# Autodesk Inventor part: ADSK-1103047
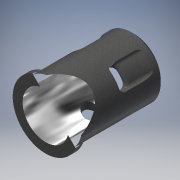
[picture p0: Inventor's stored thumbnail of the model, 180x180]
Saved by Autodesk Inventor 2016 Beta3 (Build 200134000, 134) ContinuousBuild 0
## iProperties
Shininess: 54.0
Length Units: 11269
Angle Units: 11279
Time Units: 11290
Mass Units: 11286
Length Display Precision: 2
Angle Display Precision: 2
Compacted: True
Created: 2000-07
Part Number: ADSK-1103047
Document SubType Name: Modeling
Description: ENGINE SLEEVE - REAR
Mass: 20.4003 g
Surface Area: 29.807 cm^2
Volume: 2.59876 cm^3
Density: 7.85 g/cm^3
Material: Cast Steel
Appearance: Brass
Density: 0.0
Volumn: 0.0
Area: 0.0
PropertySet Name: Model Information
Control State: 0
Master: False
Checked Out: False
Author: Autodesk, Inc.
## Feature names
1. Extrusion3
2. Fillet1
3. Revolution1
4. Fillet2
5. Sweep1
6. Fillet3
7. Fillet4
8. Mirror1
## Parameters: d0 = 18 mm, d1 = 14 mm, d2 = 27 mm, d3 = 0, d5 = 2 mm, d6 = 0, d7 = 1 mm, d8 = 1 mm, d9 = 45 deg, d10 = 0, d11 = 0, d12 = 0, d13 = 0, d15 = 0, d16 = 2 mm, d17 = -40 deg, d18 = 3 mm, d19 = 45 deg, d20 = 1.5 mm, d21 = 45 deg, d22 = 1 mm, d23 = 0, d24 = 1 mm, d25 = 1 mm, d26 = 0
